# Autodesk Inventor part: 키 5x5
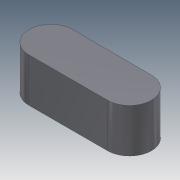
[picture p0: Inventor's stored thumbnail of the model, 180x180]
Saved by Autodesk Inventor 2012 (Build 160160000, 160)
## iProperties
Company: 한국ATC센터
Created: 2014-10
Part Number: 키 5x5
Document SubType Name: Modeling
Designer: KYOUNG IL JANG
Density: 1 g/cm^3
Mass: 0.323175 g
Surface Area: 2.9781 cm^2
Volume: 0.323175 cm^3
Material: 기본값
Author: KYOUNG IL JANG
Revision Number: 1
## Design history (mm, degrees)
sketch "스케치1"
  geometry: L1 (-4.5, -2.5)-(4.5, -2.5); L2 (4.5, 2.5)-(-4.5, 2.5); A1 r 2.5 centre (4.5, 0) between (4.5, -2.5) and (4.5, 2.5); A2 r 2.5 centre (-4.5, 0) between (-4.5, 2.5) and (-4.5, -2.5); 2 further points
  constraints: 4 end point, 4 point on circle, 4 tangent, 2 centre point, 1 horizontal, 1 horizontal alignment, 1 midpoint, 1 parallel, 1 vertical alignment
  dimensions: "d0" = 5 distance between parallel lines of L1 L2; "d1" = 14 dimension on A1 A2
extrude "돌출1" new body sketch "스케치1" stored distance "d2" = 5; taper "d3" = 0 deg
node "솔리드1"
